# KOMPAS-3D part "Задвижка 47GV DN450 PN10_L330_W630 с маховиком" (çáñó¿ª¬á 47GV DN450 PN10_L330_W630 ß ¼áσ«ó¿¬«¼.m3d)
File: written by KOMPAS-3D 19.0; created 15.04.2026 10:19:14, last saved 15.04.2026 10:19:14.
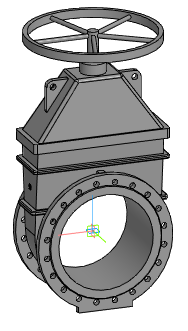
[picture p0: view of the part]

Document properties: Автор: Евгений; Полное имя файла: Z:\3.Личные\kachalov\3d для проектировщиков\2.1 Тип 47GV, 47GV.Z\Задвижка 47GV_DN40-DN600\stp_Задвижка 47GV\Задвижка 47GV DN450 PN10_L330_W630 с маховиком.m3d

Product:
- Part/product: Задвижка 47GV DN450 PN10_L330_W630 с маховиком

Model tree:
1. Операция без истории:1  (labels: Задвижка 47GV DN450 PN10_L330_W630 с маховиком)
